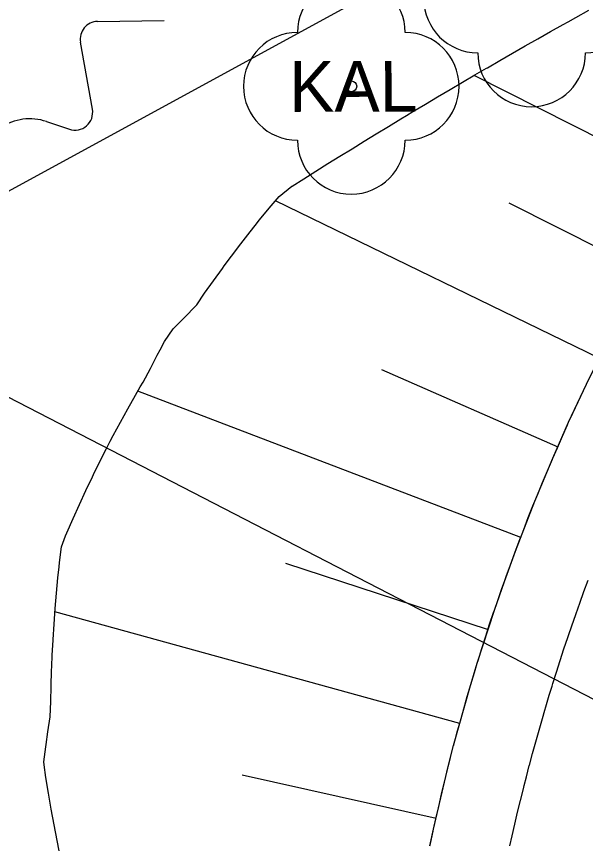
# Model space of a CAD drawing. Extents: x -564037 to -563722, y -1163561 to -1163412.
# Drawn here: x -563870.9 to -563863.63, y -1163500.32 to -1163489.75 of the extents above; entities that cross this region are included whole.
import ezdxf

# ---------------------------------------------------------------- set-up
doc = ezdxf.new("R2010")
doc.units = 0
for name, color, linetype in [('5', 7, 'Continuous'), ('Line', 7, 'Continuous'), ('podélný profil', 7, 'Continuous'), ('Vrstva 1', 7, 'Continuous'), ('Vrstva 2', 7, 'Continuous')]:
    doc.layers.add(name, color=color, linetype=linetype)

msp = doc.modelspace()

# ---------------------------------------------------------------- linework, layer by layer
for points in [[(-563870.356, -1163500.406), (-563870.382, -1163500.275), (-563870.42, -1163500.075), (-563870.457, -1163499.874), (-563870.491, -1163499.672), (-563870.524, -1163499.47), (-563870.549, -1163499.308), (-563870.552, -1163499.268), (-563870.526, -1163499.077), (-563870.522, -1163499.047), (-563870.499, -1163498.886), (-563870.469, -1163498.695), (-563870.461, -1163498.499), (-563870.458, -1163498.302), (-563870.452, -1163498.104), (-563870.45, -1163498.053), (-563870.444, -1163497.906), (-563870.434, -1163497.716), (-563870.434, -1163497.709), (-563870.421, -1163497.511), (-563870.407, -1163497.314), (-563870.39, -1163497.117), (-563870.371, -1163496.92), (-563870.357, -1163496.779), (-563870.35, -1163496.723), (-563870.327, -1163496.526), (-563870.273, -1163496.384), (-563870.256, -1163496.344), (-563870.177, -1163496.164), (-563870.097, -1163495.985), (-563870.014, -1163495.807), (-563869.93, -1163495.63), (-563869.915, -1163495.6), (-563869.843, -1163495.454), (-563869.755, -1163495.279), (-563869.702, -1163495.177), (-563869.664, -1163495.105), (-563869.572, -1163494.933), (-563869.477, -1163494.761), (-563869.381, -1163494.59), (-563869.32, -1163494.483), (-563869.283, -1163494.421), (-563869.19, -1163494.249), (-563869.102, -1163494.077), (-563869.066, -1163494.008), (-563869.011, -1163493.905), (-563868.898, -1163493.743), (-563868.754, -1163493.595), (-563868.609, -1163493.448), (-563868.599, -1163493.434), (-563868.498, -1163493.287), (-563868.385, -1163493.128), (-563868.27, -1163492.97), (-563868.246, -1163492.937), (-563868.154, -1163492.813), (-563868.036, -1163492.658), (-563867.916, -1163492.504), (-563867.85, -1163492.42), (-563867.795, -1163492.351), (-563867.672, -1163492.2), (-563867.547, -1163492.05), (-563867.383, -1163491.921), (-563867.379, -1163491.919), (-563867.23, -1163491.824), (-563867.077, -1163491.728), (-563866.923, -1163491.632), (-563866.769, -1163491.536), (-563866.615, -1163491.441), (-563866.46, -1163491.346), (-563866.305, -1163491.251), (-563866.149, -1163491.156), (-563865.992, -1163491.062), (-563865.92, -1163491.018), (-563865.836, -1163490.967), (-563865.678, -1163490.873), (-563865.521, -1163490.78), (-563865.362, -1163490.686), (-563865.204, -1163490.593), (-563865.044, -1163490.5), (-563864.898, -1163490.415), (-563864.885, -1163490.407), (-563864.725, -1163490.315), (-563864.564, -1163490.222), (-563864.403, -1163490.13), (-563864.241, -1163490.039), (-563864.079, -1163489.947), (-563863.917, -1163489.856), (-563863.856, -1163489.822), (-563863.754, -1163489.765), (-563863.59, -1163489.674)], [(-563865.619, -1163500.343), (-563865.574, -1163500.129), (-563865.385, -1163499.33), (-563865.317, -1163499.063), (-563865.111, -1163498.327), (-563865.015, -1163498.009), (-563864.797, -1163497.335), (-563864.669, -1163496.968), (-563864.528, -1163496.58), (-563864.443, -1163496.357), (-563864.28, -1163495.943), (-563864.051, -1163495.394), (-563863.848, -1163494.935), (-563863.62, -1163494.448), (-563863.373, -1163493.946), (-563863.165, -1163493.533), (-563862.713, -1163492.641), (-563862.262, -1163491.749), (-563861.987, -1163491.206), (-563861.81, -1163490.857), (-563861.359, -1163489.964), (-563861.279, -1163489.807)], [(-563865.619, -1163500.343), (-563865.613, -1163500.311), (-563865.579, -1163500.154), (-563865.574, -1163500.129), (-563865.544, -1163499.997), (-563865.508, -1163499.84), (-563865.472, -1163499.683), (-563865.434, -1163499.526), (-563865.395, -1163499.37), (-563865.385, -1163499.33), (-563865.356, -1163499.214), (-563865.317, -1163499.063), (-563865.315, -1163499.058), (-563865.274, -1163498.902), (-563865.231, -1163498.747), (-563865.188, -1163498.592), (-563865.143, -1163498.437), (-563865.111, -1163498.327), (-563865.098, -1163498.283), (-563865.052, -1163498.128), (-563865.015, -1163498.009), (-563865.004, -1163497.974), (-563864.956, -1163497.821), (-563864.907, -1163497.667), (-563864.857, -1163497.514), (-563864.806, -1163497.362), (-563864.797, -1163497.335), (-563864.754, -1163497.209), (-563864.701, -1163497.057), (-563864.669, -1163496.968), (-563864.647, -1163496.905), (-563864.592, -1163496.754), (-563864.536, -1163496.603), (-563864.48, -1163496.452), (-563864.443, -1163496.357), (-563864.422, -1163496.302), (-563864.363, -1163496.152), (-563864.304, -1163496.002), (-563864.28, -1163495.943), (-563864.243, -1163495.853), (-563864.182, -1163495.704), (-563864.12, -1163495.555), (-563864.056, -1163495.407), (-563864.051, -1163495.394), (-563863.992, -1163495.259), (-563863.927, -1163495.112), (-563863.861, -1163494.965), (-563863.848, -1163494.935), (-563863.795, -1163494.819), (-563863.727, -1163494.673), (-563863.658, -1163494.527), (-563863.62, -1163494.448)], [(-563864.597, -1163500.343), (-563864.568, -1163500.215), (-563864.534, -1163500.064), (-563864.499, -1163499.914), (-563864.462, -1163499.763), (-563864.425, -1163499.613), (-563864.416, -1163499.574), (-563864.387, -1163499.463), (-563864.35, -1163499.318), (-563864.348, -1163499.313), (-563864.308, -1163499.163), (-563864.267, -1163499.014), (-563864.226, -1163498.865), (-563864.183, -1163498.716), (-563864.152, -1163498.61), (-563864.139, -1163498.567), (-563864.095, -1163498.419), (-563864.06, -1163498.304), (-563864.049, -1163498.271), (-563864.003, -1163498.123), (-563863.956, -1163497.976), (-563863.908, -1163497.829), (-563863.858, -1163497.682), (-563863.85, -1163497.656), (-563863.808, -1163497.535), (-563863.757, -1163497.389), (-563863.727, -1163497.303), (-563863.706, -1163497.243), (-563863.653, -1163497.097), (-563863.599, -1163496.952)]]:
    msp.add_lwpolyline(points)
at = {"layer": '5'}
for p, q in [((-563897.15, -1163506.247), (-563862.812, -1163487.513)), ((-563871.424, -1163494.398), (-563841.172, -1163509.993))]:
    msp.add_line(p, q, dxfattribs=at)
at = {"layer": 'Line'}
for p, q in [((-563862.33, -1163491.884), (-563865.054, -1163490.506)), ((-563863.457, -1163494.115), (-563867.593, -1163492.106)), ((-563864.611, -1163492.132), (-563862.894, -1163492.999)), ((-563866.237, -1163494.262), (-563863.986, -1163495.248)), ((-563864.459, -1163496.404), (-563869.35, -1163494.536)), ((-563867.464, -1163496.734), (-563864.877, -1163497.582)), ((-563865.238, -1163498.779), (-563870.41, -1163497.354)), ((-563868.019, -1163499.435), (-563865.541, -1163499.991))]:
    msp.add_line(p, q, dxfattribs=at)
at = {"layer": 'podélný profil'}
for points in [[(-563869.865, -1163489.817), (-563869.014, -1163489.803)], [(-563869.931, -1163490.938), (-563870.083, -1163490.082)], [(-563870.517, -1163491.094), (-563870.225, -1163491.192)]]:
    msp.add_lwpolyline(points, dxfattribs=at)
for centre, radius, start, end in [((-563869.861, -1163490.042), 0.226, 90.9347, 190.0519), ((-563870.153, -1163490.978), 0.226, 251.5312, 10.0782), ((-563870.731, -1163491.737), 0.677, 71.5291, 123.2236)]:
    msp.add_arc(centre, radius, start, end, dxfattribs=at)
at = {"layer": 'Vrstva 2'}
msp.add_circle((-563866.624, -1163490.645), 0.0688, dxfattribs=at)
for centre, start, end in [((-563865.009, -1163489.529), 90, 270), ((-563863.633, -1163489.529), 270, 90), ((-563866.624, -1163489.957), 0, 180), ((-563867.312, -1163490.645), 90, 270), ((-563865.936, -1163490.645), 270, 90), ((-563864.321, -1163490.217), 180, 0), ((-563866.624, -1163491.333), 180, 0)]:
    msp.add_arc(centre, 0.688, start, end, dxfattribs=at)

# ---------------------------------------------------------------- texts
at = {"layer": 'Vrstva 1'}
msp.add_text('KAL', height=0.648, rotation=0.1546, dxfattribs=at).set_placement((-563867.417, -1163490.971))

doc.saveas('drawing.dxf')
